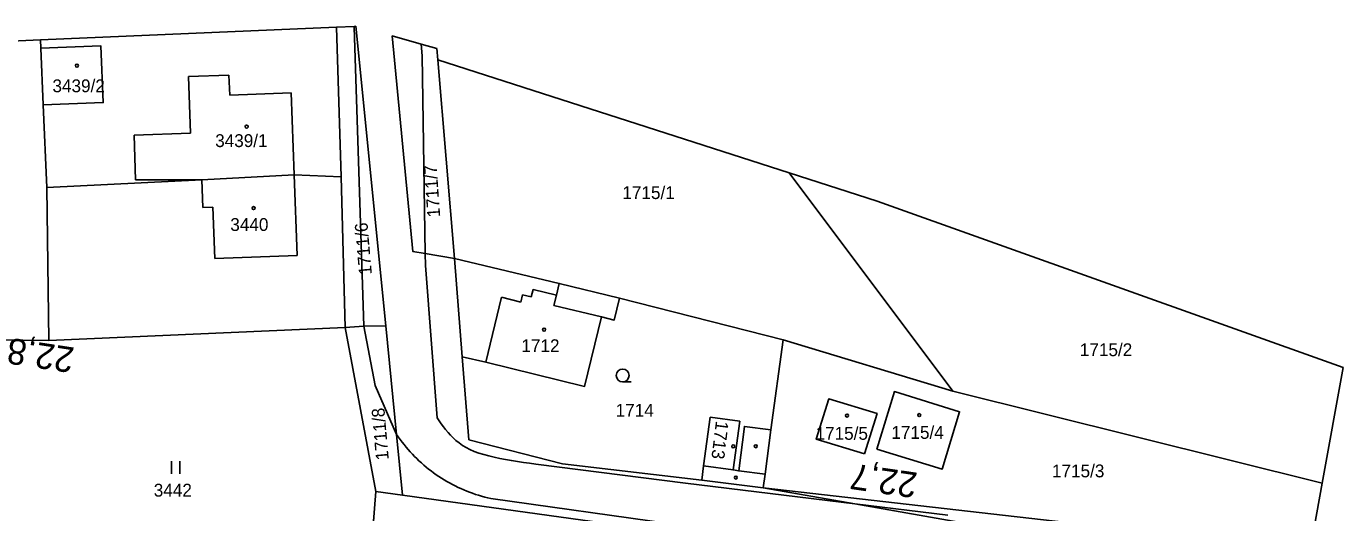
# Model space of a CAD drawing. Extents: x -757895 to -757311, y -1060303 to -1059942.
# Drawn here: x -757679.5 to -757525.7, y -1060109.2 to -1060052.3 of the extents above; entities that cross this region are included whole.
import ezdxf

# ---------------------------------------------------------------- set-up
doc = ezdxf.new("R2010")
doc.units = 0
for name, color, linetype in [('_hektaky', 7, 'Continuous'), ('Vrstva 55', 7, 'Continuous'), ('Vrstva 56', 7, 'Continuous'), ('Vrstva 57', 7, 'Continuous'), ('Vrstva 58', 7, 'Continuous'), ('Vrstva 59', 7, 'Continuous')]:
    doc.layers.add(name, color=color, linetype=linetype)

msp = doc.modelspace()

# ---------------------------------------------------------------- linework, layer by layer
at = {"layer": 'Vrstva 55'}
for p, q in [((-757640.91, -1060052.31), (-757637.42, -1060087.32)), ((-757688.39, -1060054.34), (-757677.84, -1060053.89)), ((-757677.84, -1060053.89), (-757643.18, -1060052.41)), ((-757677.8, -1060054.85), (-757677.84, -1060053.89)), ((-757643.18, -1060052.41), (-757642.66, -1060069.92)), ((-757643.18, -1060052.41), (-757642.66, -1060069.92)), ((-757677.8, -1060054.85), (-757677.51, -1060061.51)), ((-757631.34, -1060056.24), (-757631.45, -1060054.91)), ((-757629.39, -1060079.46), (-757631.34, -1060056.24)), ((-757590.19, -1060069.45), (-757631.34, -1060056.24)), ((-757677.1, -1060071.14), (-757677.51, -1060061.51)), ((-757642.66, -1060069.92), (-757642.17, -1060087.53)), ((-757642.66, -1060069.92), (-757642.17, -1060087.53)), ((-757571.04, -1060094.99), (-757590.19, -1060069.45)), ((-757579.91, -1060072.75), (-757590.19, -1060069.45)), ((-757677.1, -1060071.14), (-757676.88, -1060089.06)), ((-757525.35, -1060092.2), (-757579.91, -1060072.75)), ((-757628.47, -1060090.94), (-757629.39, -1060079.46)), ((-757590.9, -1060088.98), (-757610.05, -1060084.09)), ((-757676.88, -1060089.06), (-757642.17, -1060087.53)), ((-757642.17, -1060087.53), (-757638.59, -1060106.69)), ((-757642.17, -1060087.53), (-757638.59, -1060106.69)), ((-757689.45, -1060088.87), (-757676.88, -1060089.06)), ((-757592.34, -1060099.49), (-757590.9, -1060088.98)), ((-757590.9, -1060088.98), (-757571.04, -1060094.99)), ((-757527.8, -1060105.72), (-757525.35, -1060092.2)), ((-757571.04, -1060094.99), (-757527.8, -1060105.72)), ((-757592.99, -1060104.69), (-757592.34, -1060099.49)), ((-757593.23, -1060106.29), (-757600.41, -1060105.4)), ((-757593.23, -1060106.29), (-757592.99, -1060104.69)), ((-757530.66, -1060121.48), (-757527.8, -1060105.72)), ((-757638.59, -1060106.69), (-757639.93, -1060124.17)), ((-757638.59, -1060106.69), (-757639.93, -1060124.17)), ((-757635.45, -1060107.13), (-757638.59, -1060106.69))]:
    msp.add_line(p, q, dxfattribs=at)
for points in [[(-757643.18, -1060052.41), (-757641.12, -1060052.32), (-757640.91, -1060052.31)], [(-757643.18, -1060052.41), (-757642.66, -1060069.92), (-757642.17, -1060087.53), (-757638.59, -1060106.69), (-757639.93, -1060124.17), (-757639.03, -1060128.02), (-757637.9, -1060132.49), (-757634.26, -1060145.96), (-757630.94, -1060158.73), (-757631.18, -1060185.19), (-757631.2, -1060187.35)], [(-757629.39, -1060079.46), (-757632.79, -1060078.88), (-757634.26, -1060078.63), (-757636.66, -1060053.43), (-757633.26, -1060054.4), (-757631.45, -1060054.91)], [(-757677.51, -1060061.51), (-757670.5, -1060061.23), (-757670.77, -1060054.6), (-757677.8, -1060054.85)], [(-757642.66, -1060069.92), (-757648.14, -1060069.67), (-757658.97, -1060070.25), (-757677.1, -1060071.14)], [(-757610.05, -1060084.09), (-757617.11, -1060082.38), (-757629.39, -1060079.46)], [(-757628.47, -1060090.94), (-757625.72, -1060091.6), (-757614.14, -1060094.41), (-757612.17, -1060086.29), (-757610.67, -1060086.66), (-757610.05, -1060084.09)], [(-757642.17, -1060087.53), (-757639.97, -1060087.39), (-757637.42, -1060087.32)], [(-757637.42, -1060087.32), (-757636.16, -1060100.03), (-757635.45, -1060107.13)], [(-757600.41, -1060105.4), (-757616.74, -1060103.46), (-757627.69, -1060100.66), (-757628.47, -1060090.94)], [(-757579.94, -1060101.75), (-757572.27, -1060104.08), (-757570.24, -1060097.38), (-757577.88, -1060095.03), (-757579.94, -1060101.75)], [(-757581.36, -1060102.3), (-757579.91, -1060097.6), (-757585.56, -1060095.88), (-757587.03, -1060100.59), (-757581.36, -1060102.3)], [(-757592.34, -1060099.49), (-757595.44, -1060099.1), (-757596.09, -1060104.3), (-757596.77, -1060104.18), (-757595.99, -1060098.5), (-757599.43, -1060098.03), (-757600.22, -1060103.7), (-757600.41, -1060105.4)], [(-757604.11, -1060111.45), (-757614.37, -1060110.07), (-757635.45, -1060107.13)], [(-757538.3, -1060115.83), (-757542.65, -1060115.17), (-757582.51, -1060108.15), (-757593.23, -1060106.29)], [(-757538.3, -1060115.83), (-757541.05, -1060113.79), (-757553.6, -1060110.8), (-757593.23, -1060106.29)]]:
    msp.add_lwpolyline(points, dxfattribs=at)
at = {"layer": 'Vrstva 56'}
for p, q in [((-757641.12, -1060052.42), (-757641.12, -1060052.32)), ((-757641.12, -1060052.42), (-757639.97, -1060087.39)), ((-757633.15, -1060055.76), (-757633.26, -1060054.4)), ((-757632.79, -1060078.88), (-757633.15, -1060055.76)), ((-757655.79, -1060058.03), (-757660.5, -1060058.19)), ((-757660.5, -1060058.19), (-757660.27, -1060064.81)), ((-757655.69, -1060060.37), (-757655.79, -1060058.03)), ((-757648.49, -1060060.1), (-757655.69, -1060060.37)), ((-757648.14, -1060069.67), (-757648.49, -1060060.1)), ((-757660.27, -1060064.81), (-757666.88, -1060065.04)), ((-757666.88, -1060065.04), (-757666.7, -1060070.26)), ((-757666.7, -1060070.26), (-757658.97, -1060070.25)), ((-757658.97, -1060070.25), (-757658.85, -1060073.5)), ((-757647.79, -1060079.11), (-757648.14, -1060069.67)), ((-757658.85, -1060073.5), (-757657.65, -1060073.45)), ((-757657.65, -1060073.45), (-757657.42, -1060079.47)), ((-757657.42, -1060079.47), (-757647.79, -1060079.11)), ((-757632.77, -1060080.29), (-757632.79, -1060078.88)), ((-757631.4, -1060098.08), (-757632.77, -1060080.29)), ((-757620.38, -1060083.96), (-757620.16, -1060083.08)), ((-757620.16, -1060083.08), (-757617.44, -1060083.74)), ((-757617.11, -1060082.38), (-757617.44, -1060083.74)), ((-757625.72, -1060091.6), (-757623.88, -1060084)), ((-757623.88, -1060084), (-757621.6, -1060084.55)), ((-757621.6, -1060084.55), (-757621.4, -1060083.71)), ((-757621.4, -1060083.71), (-757620.38, -1060083.96)), ((-757617.44, -1060083.74), (-757617.73, -1060084.95)), ((-757617.73, -1060084.95), (-757612.17, -1060086.29)), ((-757639.97, -1060087.39), (-757638.66, -1060094.33)), ((-757638.66, -1060094.33), (-757636.16, -1060100.03)), ((-757602.33, -1060105.73), (-757619.86, -1060103.51)), ((-757596.77, -1060104.18), (-757600.22, -1060103.7)), ((-757592.99, -1060104.69), (-757596.09, -1060104.3)), ((-757582.51, -1060108.15), (-757602.33, -1060105.73)), ((-757625.12, -1060107.53), (-757604, -1060110.48)), ((-757571.64, -1060109.48), (-757582.51, -1060108.15))]:
    msp.add_line(p, q, dxfattribs=at)
for points in [[(-757619.86, -1060103.51), (-757620.58, -1060103.41), (-757621.3, -1060103.31), (-757622.01, -1060103.2), (-757622.71, -1060103.09), (-757623.4, -1060102.97), (-757624.07, -1060102.84), (-757624.72, -1060102.71), (-757625.35, -1060102.55), (-757625.95, -1060102.39), (-757626.52, -1060102.21), (-757627.06, -1060102.02), (-757627.56, -1060101.8), (-757628.02, -1060101.56), (-757628.45, -1060101.31), (-757628.84, -1060101.03), (-757629.2, -1060100.75), (-757629.53, -1060100.44), (-757629.84, -1060100.13), (-757630.13, -1060099.8), (-757630.41, -1060099.47), (-757630.67, -1060099.13), (-757630.92, -1060098.78), (-757631.16, -1060098.43), (-757631.4, -1060098.08)], [(-757625.12, -1060107.53), (-757625.48, -1060107.45), (-757625.84, -1060107.36), (-757626.2, -1060107.26), (-757626.55, -1060107.15), (-757626.9, -1060107.04), (-757627.25, -1060106.92), (-757627.6, -1060106.79), (-757627.94, -1060106.66), (-757628.28, -1060106.52), (-757628.62, -1060106.37), (-757628.96, -1060106.22), (-757629.29, -1060106.06), (-757629.62, -1060105.89), (-757629.95, -1060105.71), (-757630.27, -1060105.53), (-757630.58, -1060105.34), (-757630.9, -1060105.15), (-757631.21, -1060104.95), (-757631.51, -1060104.74), (-757631.82, -1060104.52), (-757632.11, -1060104.3), (-757632.41, -1060104.08), (-757632.69, -1060103.85), (-757632.97, -1060103.61), (-757633.25, -1060103.36), (-757633.53, -1060103.11), (-757633.79, -1060102.86), (-757634.06, -1060102.6), (-757634.31, -1060102.33), (-757634.56, -1060102.06), (-757634.81, -1060101.79), (-757635.05, -1060101.51), (-757635.28, -1060101.22), (-757635.51, -1060100.93), (-757635.73, -1060100.63), (-757635.95, -1060100.33), (-757636.16, -1060100.03)]]:
    msp.add_lwpolyline(points, dxfattribs=at)
at = {"layer": 'Vrstva 58'}
for p, q in [((-757609.69, -1060093.89), (-757608.69, -1060093.89)), ((-757662.51, -1060103.14), (-757662.51, -1060104.64)), ((-757661.51, -1060104.64), (-757661.51, -1060103.14))]:
    msp.add_line(p, q, dxfattribs=at)
msp.add_circle((-757609.69, -1060093.14), 0.75, dxfattribs=at)
at = {"layer": 'Vrstva 59'}
for centre in [(-757673.58, -1060056.91), (-757653.71, -1060064.04), (-757652.89, -1060073.57), (-757618.88, -1060087.78), (-757583.42, -1060097.83), (-757574.97, -1060097.77), (-757596.74, -1060101.43), (-757594.1, -1060101.41), (-757596.44, -1060105.07)]:
    msp.add_circle(centre, 0.175, dxfattribs=at)

# ---------------------------------------------------------------- texts
at = {"layer": '_hektaky'}
for s, rotation, p in [('22,8', 171.4001, (-757673.76, -1060089.9)), ('22,7', 171.7816, (-757575.06, -1060104.53))]:
    msp.add_text(s, height=3, rotation=rotation, dxfattribs=at).set_placement(p)
at = {"layer": 'Vrstva 57'}
for s, p in [('3439/2', (-757676.44, -1060060.02)), ('3439/1', (-757657.39, -1060066.43)), ('1715/1', (-757609.72, -1060072.51)), ('3440', (-757655.62, -1060076.24)), ('1712', (-757621.54, -1060090.41)), ('1715/2', (-757556.17, -1060090.88)), ('1714', (-757610.51, -1060097.96)), ('1715/5', (-757587.11, -1060100.66)), ('1715/4', (-757578.23, -1060100.55)), ('1715/3', (-757559.43, -1060105.05)), ('3442', (-757664.58, -1060107.3))]:
    msp.add_text(s, height=1.5, dxfattribs=at).set_placement(p)
for s, rotation, p in [('1711/7', 94, (-757631.04, -1060074.59)), ('1711/6', 95, (-757639.04, -1060081.32)), ('1711/8', 95, (-757637.06, -1060102.98)), ('1713', 263, (-757598.76, -1060098.4))]:
    msp.add_text(s, height=1.5, rotation=rotation, dxfattribs=at).set_placement(p)

doc.saveas('drawing.dxf')
